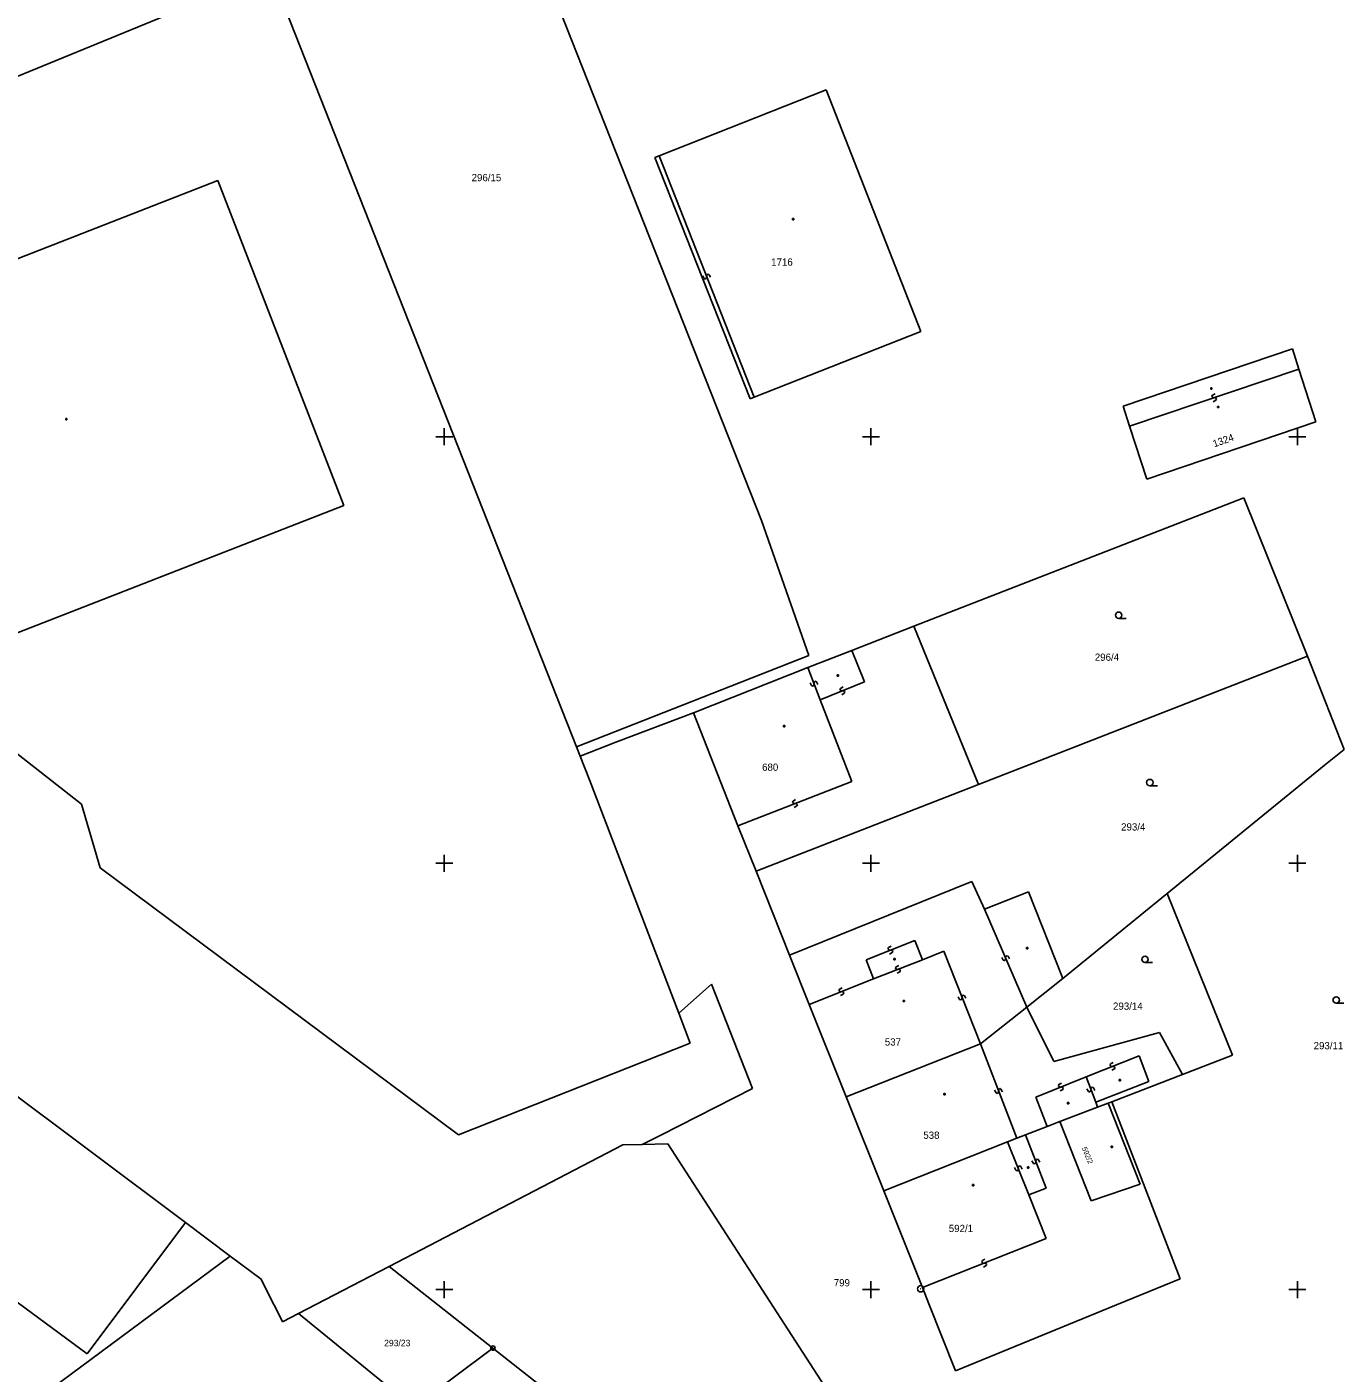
# Model space of a CAD drawing. Extents: x -492379 to -491966, y -1126153 to -1125860.
# Drawn here: x -492059.4 to -491966.7, y -1126055.9 to -1125961.2 of the extents above; entities that cross this region are included whole.
import ezdxf

# ---------------------------------------------------------------- set-up
doc = ezdxf.new("R2010")
doc.units = 0
doc.layers.add('katastrální mapa', color=7, linetype='Continuous')
doc.layers.add('síť', color=7, linetype='Continuous')

msp = doc.modelspace()

# ---------------------------------------------------------------- linework, layer by layer
at = {"layer": 'katastrální mapa'}
for p, q in [((-492033.05, -1125931.66), (-492007.69, -1125995.9)), ((-492049.8, -1125938.02), (-492020.7, -1126011.81)), ((-492074.82, -1125970.7), (-492046.06, -1125958.91)), ((-492014.89, -1125970.24), (-492003.15, -1125965.6)), ((-492003.15, -1125965.6), (-491996.49, -1125982.6)), ((-492015.19, -1125970.36), (-492014.89, -1125970.24)), ((-492015.19, -1125970.36), (-492008.49, -1125987.33)), ((-492014.89, -1125970.24), (-492008.21, -1125987.22)), ((-492063.85, -1125978.97), (-492045.92, -1125971.96)), ((-492045.92, -1125971.96), (-492037.06, -1125994.84)), ((-492005.52, -1125974.64), (-492005.43, -1125974.64)), ((-492005.52, -1125974.73), (-492005.52, -1125974.64)), ((-492005.43, -1125974.73), (-492005.52, -1125974.73)), ((-492005.43, -1125974.64), (-492005.43, -1125974.73)), ((-492011.72, -1125978.86), (-492011.83, -1125978.68)), ((-492011.65, -1125978.9), (-492011.72, -1125978.86)), ((-492011.59, -1125978.87), (-492011.65, -1125978.9)), ((-492011.56, -1125978.8), (-492011.59, -1125978.87)), ((-492011.54, -1125978.66), (-492011.56, -1125978.8)), ((-492011.51, -1125978.59), (-492011.54, -1125978.66)), ((-492011.45, -1125978.56), (-492011.51, -1125978.59)), ((-492011.38, -1125978.6), (-492011.45, -1125978.56)), ((-492011.27, -1125978.78), (-492011.38, -1125978.6)), ((-492008.21, -1125987.22), (-491996.49, -1125982.6)), ((-491982.25, -1125987.84), (-491970.35, -1125983.81)), ((-491970.35, -1125983.81), (-491969.9, -1125985.24)), ((-491981.8, -1125989.26), (-491969.9, -1125985.24)), ((-491969.9, -1125985.24), (-491968.71, -1125988.95)), ((-491976.1, -1125986.56), (-491976.01, -1125986.56)), ((-491976.1, -1125986.65), (-491976.1, -1125986.56)), ((-491976.01, -1125986.56), (-491976.01, -1125986.65)), ((-492008.49, -1125987.33), (-492008.21, -1125987.22)), ((-491976.01, -1125986.65), (-491976.1, -1125986.65)), ((-491975.97, -1125987.07), (-491976.01, -1125987.15)), ((-491976.01, -1125987.15), (-491975.99, -1125987.2)), ((-491975.99, -1125987.2), (-491975.92, -1125987.24)), ((-491975.78, -1125986.97), (-491975.97, -1125987.07)), ((-491975.92, -1125987.24), (-491975.78, -1125987.26)), ((-491975.73, -1125987.43), (-491975.92, -1125987.53)), ((-491975.78, -1125987.26), (-491975.71, -1125987.3)), ((-491975.69, -1125987.35), (-491975.73, -1125987.43)), ((-491975.71, -1125987.3), (-491975.69, -1125987.35)), ((-491982.25, -1125987.84), (-491981.8, -1125989.26)), ((-491975.62, -1125987.86), (-491975.53, -1125987.86)), ((-491975.62, -1125987.95), (-491975.62, -1125987.86)), ((-491975.53, -1125987.95), (-491975.62, -1125987.95)), ((-491975.53, -1125987.86), (-491975.53, -1125987.95)), ((-492056.63, -1125988.72), (-492056.54, -1125988.72)), ((-492056.63, -1125988.81), (-492056.63, -1125988.72)), ((-492056.54, -1125988.81), (-492056.63, -1125988.81)), ((-492056.54, -1125988.72), (-492056.54, -1125988.81)), ((-491981.8, -1125989.26), (-491980.6, -1125992.98)), ((-491980.6, -1125992.98), (-491968.71, -1125988.95)), ((-492062.15, -1126004.61), (-492037.06, -1125994.84)), ((-491996.98, -1126003.33), (-491973.76, -1125994.3)), ((-491973.76, -1125994.3), (-491969.3, -1126005.44)), ((-492007.69, -1125995.9), (-492004.36, -1126005.38)), ((-492001.35, -1126005.03), (-491996.98, -1126003.33)), ((-491996.98, -1126003.33), (-491992.42, -1126014.46)), ((-491982.57, -1126002.78), (-491982.04, -1126002.78)), ((-492020.7, -1126011.81), (-492004.36, -1126005.38)), ((-492004.44, -1126006.23), (-492001.35, -1126005.03)), ((-492001.35, -1126005.03), (-492000.45, -1126007.23)), ((-491992.42, -1126014.46), (-491969.3, -1126005.44)), ((-491969.3, -1126005.44), (-491966.72, -1126011.99)), ((-492012.48, -1126009.42), (-492004.44, -1126006.23)), ((-492004.44, -1126006.23), (-492003.56, -1126008.51)), ((-492004.17, -1126007.5), (-492004.28, -1126007.32)), ((-492003.99, -1126007.3), (-492004.01, -1126007.44)), ((-492003.96, -1126007.23), (-492003.99, -1126007.3)), ((-492003.9, -1126007.2), (-492003.96, -1126007.23)), ((-492003.83, -1126007.24), (-492003.9, -1126007.2)), ((-492003.72, -1126007.42), (-492003.83, -1126007.24)), ((-492003.56, -1126008.51), (-492000.45, -1126007.23)), ((-492002.36, -1126006.74), (-492002.27, -1126006.74)), ((-492002.36, -1126006.83), (-492002.36, -1126006.74)), ((-492002.27, -1126006.83), (-492002.36, -1126006.83)), ((-492002.27, -1126006.74), (-492002.27, -1126006.83)), ((-492004.1, -1126007.54), (-492004.17, -1126007.5)), ((-492004.04, -1126007.51), (-492004.1, -1126007.54)), ((-492004.01, -1126007.44), (-492004.04, -1126007.51)), ((-492002.14, -1126007.7), (-492002.17, -1126007.78)), ((-492002.17, -1126007.78), (-492002.15, -1126007.83)), ((-492002.15, -1126007.83), (-492002.07, -1126007.87)), ((-492001.96, -1126007.59), (-492002.14, -1126007.7)), ((-492002.07, -1126007.87), (-492001.94, -1126007.87)), ((-492001.87, -1126008.04), (-492002.05, -1126008.15)), ((-492001.94, -1126007.87), (-492001.86, -1126007.91)), ((-492001.84, -1126007.96), (-492001.87, -1126008.04)), ((-492001.86, -1126007.91), (-492001.84, -1126007.96)), ((-492003.56, -1126008.51), (-492001.33, -1126014.24)), ((-492017.93, -1126011.48), (-492012.48, -1126009.42)), ((-492012.48, -1126009.42), (-492009.35, -1126017.36)), ((-492006.14, -1126010.32), (-492006.05, -1126010.32)), ((-492006.14, -1126010.41), (-492006.14, -1126010.32)), ((-492006.05, -1126010.41), (-492006.14, -1126010.41)), ((-492006.05, -1126010.32), (-492006.05, -1126010.41)), ((-492060.51, -1126011.92), (-492055.51, -1126015.84)), ((-492020.7, -1126011.81), (-492020.44, -1126012.46)), ((-492020.44, -1126012.46), (-492017.93, -1126011.48)), ((-491968.11, -1126013.12), (-491966.72, -1126011.99)), ((-492020.44, -1126012.46), (-492019.8, -1126014.14)), ((-491979.16, -1126022.13), (-491968.11, -1126013.12)), ((-492019.8, -1126014.14), (-492013.51, -1126030.54)), ((-492009.35, -1126017.36), (-492001.33, -1126014.24)), ((-491995.5, -1126015.66), (-491992.42, -1126014.46)), ((-491980.38, -1126014.55), (-491979.85, -1126014.55)), ((-492055.51, -1126015.84), (-492054.2, -1126020.33)), ((-492008.07, -1126020.56), (-491995.5, -1126015.66)), ((-492005.47, -1126015.63), (-492005.51, -1126015.7)), ((-492005.51, -1126015.7), (-492005.48, -1126015.76)), ((-492005.48, -1126015.76), (-492005.41, -1126015.79)), ((-492005.29, -1126015.52), (-492005.47, -1126015.63)), ((-492005.41, -1126015.79), (-492005.27, -1126015.81)), ((-492005.27, -1126015.81), (-492005.2, -1126015.84)), ((-492005.17, -1126015.9), (-492005.21, -1126015.97)), ((-492005.2, -1126015.84), (-492005.17, -1126015.9)), ((-492005.21, -1126015.97), (-492005.39, -1126016.08)), ((-492009.35, -1126017.36), (-492008.07, -1126020.56)), ((-492054.2, -1126020.33), (-492029.01, -1126039.11)), ((-492008.07, -1126020.56), (-492005.72, -1126026.47)), ((-492005.72, -1126026.47), (-491992.9, -1126021.28)), ((-491992.9, -1126021.28), (-491992, -1126023.23)), ((-491992, -1126023.23), (-491988.91, -1126022.01)), ((-491988.91, -1126022.01), (-491986.51, -1126028.12)), ((-491986.51, -1126028.12), (-491979.16, -1126022.13)), ((-491979.16, -1126022.13), (-491974.57, -1126033.5)), ((-491992, -1126023.23), (-491989.04, -1126030.13)), ((-492000.34, -1126026.79), (-491996.92, -1126025.44)), ((-491998.76, -1126025.94), (-491998.8, -1126026.02)), ((-491998.8, -1126026.02), (-491998.77, -1126026.08)), ((-491998.77, -1126026.08), (-491998.7, -1126026.11)), ((-491998.58, -1126025.84), (-491998.76, -1126025.94)), ((-491998.7, -1126026.11), (-491998.56, -1126026.12)), ((-491998.5, -1126026.29), (-491998.68, -1126026.39)), ((-491998.56, -1126026.12), (-491998.49, -1126026.15)), ((-491998.46, -1126026.21), (-491998.5, -1126026.29)), ((-491998.49, -1126026.15), (-491998.46, -1126026.21)), ((-491996.92, -1126025.44), (-491996.38, -1126026.79)), ((-491996.38, -1126026.79), (-491994.88, -1126026.19)), ((-491994.88, -1126026.19), (-491992.3, -1126032.71)), ((-491989.06, -1126025.94), (-491988.97, -1126025.94)), ((-491989.06, -1126026.03), (-491989.06, -1126025.94)), ((-491988.97, -1126026.03), (-491989.06, -1126026.03)), ((-491988.97, -1126025.94), (-491988.97, -1126026.03)), ((-492005.72, -1126026.47), (-492004.34, -1126029.93)), ((-492000.34, -1126026.79), (-491999.81, -1126028.14)), ((-491999.81, -1126028.14), (-491996.38, -1126026.79)), ((-491998.39, -1126026.71), (-491998.3, -1126026.71)), ((-491998.39, -1126026.8), (-491998.39, -1126026.71)), ((-491998.3, -1126026.8), (-491998.39, -1126026.8)), ((-491998.3, -1126026.71), (-491998.3, -1126026.8)), ((-491998.23, -1126027.29), (-491998.26, -1126027.37)), ((-491998.04, -1126027.19), (-491998.23, -1126027.29)), ((-491990.69, -1126026.82), (-491990.8, -1126026.64)), ((-491990.61, -1126026.85), (-491990.69, -1126026.82)), ((-491990.56, -1126026.83), (-491990.61, -1126026.85)), ((-491990.52, -1126026.75), (-491990.56, -1126026.83)), ((-491990.48, -1126026.53), (-491990.52, -1126026.61)), ((-491990.52, -1126026.61), (-491990.52, -1126026.75)), ((-491990.43, -1126026.51), (-491990.48, -1126026.53)), ((-491990.35, -1126026.54), (-491990.43, -1126026.51)), ((-491990.24, -1126026.72), (-491990.35, -1126026.54)), ((-491980.72, -1126026.99), (-491980.19, -1126026.99)), ((-492004.34, -1126029.93), (-491999.81, -1126028.14)), ((-491998.26, -1126027.37), (-491998.24, -1126027.43)), ((-491998.24, -1126027.43), (-491998.16, -1126027.46)), ((-491998.16, -1126027.46), (-491998.03, -1126027.47)), ((-491997.96, -1126027.64), (-491998.15, -1126027.74)), ((-491998.03, -1126027.47), (-491997.95, -1126027.5)), ((-491997.93, -1126027.56), (-491997.96, -1126027.64)), ((-491997.95, -1126027.5), (-491997.93, -1126027.56)), ((-491989.04, -1126030.13), (-491986.51, -1126028.12)), ((-492013.51, -1126030.54), (-492011.21, -1126028.51)), ((-492011.21, -1126028.51), (-492008.32, -1126035.85)), ((-492002.21, -1126028.86), (-492002.24, -1126028.94)), ((-492002.24, -1126028.94), (-492002.22, -1126029)), ((-492002.22, -1126029), (-492002.14, -1126029.03)), ((-492002.02, -1126028.76), (-492002.21, -1126028.86)), ((-492002.14, -1126029.03), (-492002.01, -1126029.04)), ((-492002.01, -1126029.04), (-492001.93, -1126029.07)), ((-492001.91, -1126029.13), (-492001.94, -1126029.21)), ((-492001.93, -1126029.07), (-492001.91, -1126029.13)), ((-492004.34, -1126029.93), (-492001.74, -1126036.44)), ((-492001.94, -1126029.21), (-492002.13, -1126029.31)), ((-491997.73, -1126029.65), (-491997.64, -1126029.65)), ((-491997.73, -1126029.74), (-491997.73, -1126029.65)), ((-491997.64, -1126029.74), (-491997.73, -1126029.74)), ((-491997.64, -1126029.65), (-491997.64, -1126029.74)), ((-491993.76, -1126029.58), (-491993.87, -1126029.4)), ((-491993.69, -1126029.62), (-491993.76, -1126029.58)), ((-491993.63, -1126029.59), (-491993.69, -1126029.62)), ((-491993.6, -1126029.52), (-491993.63, -1126029.59)), ((-491993.58, -1126029.38), (-491993.6, -1126029.52)), ((-491993.55, -1126029.31), (-491993.58, -1126029.38)), ((-491993.49, -1126029.28), (-491993.55, -1126029.31)), ((-491993.42, -1126029.32), (-491993.49, -1126029.28)), ((-491993.31, -1126029.5), (-491993.42, -1126029.32)), ((-491992.3, -1126032.71), (-491989.04, -1126030.13)), ((-491989.04, -1126030.13), (-491987.14, -1126033.96)), ((-491967.27, -1126029.85), (-491966.74, -1126029.85)), ((-492068.35, -1126030.18), (-492048.21, -1126045.28)), ((-492013.51, -1126030.54), (-492012.7, -1126032.67)), ((-491987.14, -1126033.96), (-491979.71, -1126031.9)), ((-491979.71, -1126031.9), (-491978.09, -1126034.86)), ((-492029.01, -1126039.11), (-492012.7, -1126032.67)), ((-492001.74, -1126036.44), (-491992.3, -1126032.71)), ((-491992.3, -1126032.71), (-491989.74, -1126039.34)), ((-491984.87, -1126035.04), (-491981.14, -1126033.55)), ((-491981.14, -1126033.55), (-491980.44, -1126035.36)), ((-491978.09, -1126034.86), (-491974.57, -1126033.5)), ((-491983.14, -1126034.12), (-491983.17, -1126034.2)), ((-491983.17, -1126034.2), (-491983.15, -1126034.26)), ((-491983.15, -1126034.26), (-491983.07, -1126034.29)), ((-491982.95, -1126034.02), (-491983.14, -1126034.12)), ((-491983.07, -1126034.29), (-491982.94, -1126034.3)), ((-491982.87, -1126034.47), (-491983.06, -1126034.57)), ((-491983.06, -1126036.78), (-491978.09, -1126034.86)), ((-491982.94, -1126034.3), (-491982.86, -1126034.33)), ((-491982.84, -1126034.39), (-491982.87, -1126034.47)), ((-491982.86, -1126034.33), (-491982.84, -1126034.39)), ((-491988.41, -1126036.45), (-491984.87, -1126035.04)), ((-491986.77, -1126035.57), (-491986.81, -1126035.65)), ((-491986.81, -1126035.65), (-491986.78, -1126035.71)), ((-491986.78, -1126035.71), (-491986.71, -1126035.74)), ((-491986.59, -1126035.47), (-491986.77, -1126035.57)), ((-491986.71, -1126035.74), (-491986.57, -1126035.75)), ((-491986.57, -1126035.75), (-491986.5, -1126035.78)), ((-491986.5, -1126035.78), (-491986.47, -1126035.84)), ((-491984.87, -1126035.04), (-491984.18, -1126036.82)), ((-491984.48, -1126035.79), (-491984.52, -1126035.86)), ((-491984.43, -1126035.76), (-491984.48, -1126035.79)), ((-491984.35, -1126035.8), (-491984.43, -1126035.76)), ((-491984.25, -1126035.98), (-491984.35, -1126035.8)), ((-491984.18, -1126036.82), (-491980.44, -1126035.36)), ((-491982.54, -1126035.21), (-491982.45, -1126035.21)), ((-491982.54, -1126035.3), (-491982.54, -1126035.21)), ((-491982.45, -1126035.3), (-491982.54, -1126035.3)), ((-491982.45, -1126035.21), (-491982.45, -1126035.3)), ((-492014.77, -1126039.13), (-492008.32, -1126035.85)), ((-492001.74, -1126036.44), (-491999.1, -1126043.04)), ((-491994.87, -1126036.21), (-491994.78, -1126036.21)), ((-491994.87, -1126036.3), (-491994.87, -1126036.21)), ((-491994.78, -1126036.3), (-491994.87, -1126036.3)), ((-491994.78, -1126036.21), (-491994.78, -1126036.3)), ((-491991.19, -1126036.16), (-491991.3, -1126035.97)), ((-491991.12, -1126036.19), (-491991.19, -1126036.16)), ((-491991.06, -1126036.17), (-491991.12, -1126036.19)), ((-491991.03, -1126036.09), (-491991.06, -1126036.17)), ((-491991.01, -1126035.96), (-491991.03, -1126036.09)), ((-491990.98, -1126035.88), (-491991.01, -1126035.96)), ((-491990.92, -1126035.86), (-491990.98, -1126035.88)), ((-491990.85, -1126035.89), (-491990.92, -1126035.86)), ((-491990.74, -1126036.08), (-491990.85, -1126035.89)), ((-491988.41, -1126036.45), (-491987.61, -1126038.53)), ((-491986.51, -1126035.92), (-491986.69, -1126036.02)), ((-491986.47, -1126035.84), (-491986.51, -1126035.92)), ((-491984.7, -1126036.06), (-491984.8, -1126035.88)), ((-491984.62, -1126036.1), (-491984.7, -1126036.06)), ((-491984.57, -1126036.07), (-491984.62, -1126036.1)), ((-491984.53, -1126036), (-491984.57, -1126036.07)), ((-491984.52, -1126035.86), (-491984.53, -1126036)), ((-491986.71, -1126038.18), (-491984.05, -1126037.16)), ((-491986.16, -1126036.84), (-491986.07, -1126036.84)), ((-491986.16, -1126036.93), (-491986.16, -1126036.84)), ((-491986.07, -1126036.93), (-491986.16, -1126036.93)), ((-491986.07, -1126036.84), (-491986.07, -1126036.93)), ((-491984.18, -1126036.82), (-491984.05, -1126037.16)), ((-491984.05, -1126037.16), (-491983.31, -1126036.87)), ((-491983.31, -1126036.87), (-491983.06, -1126036.78)), ((-491983.31, -1126036.87), (-491981.05, -1126042.57)), ((-491983.06, -1126036.78), (-491978.24, -1126049.25)), ((-491989.13, -1126039.11), (-491987.61, -1126038.53)), ((-491987.61, -1126038.53), (-491986.71, -1126038.18)), ((-491986.71, -1126038.18), (-491984.5, -1126043.75)), ((-492016.08, -1126039.79), (-492014.77, -1126039.13)), ((-491999.1, -1126043.04), (-491990.38, -1126039.59)), ((-491990.38, -1126039.59), (-491989.74, -1126039.34)), ((-491990.38, -1126039.59), (-491988.89, -1126043.34)), ((-491989.74, -1126039.34), (-491989.13, -1126039.11)), ((-491989.13, -1126039.11), (-491987.67, -1126042.86)), ((-492033.88, -1126048.37), (-492017.45, -1126039.82)), ((-492017.45, -1126039.82), (-492016.08, -1126039.79)), ((-492016.08, -1126039.79), (-492014.28, -1126039.75)), ((-492014.28, -1126039.75), (-491999, -1126063.33)), ((-491983.1, -1126039.91), (-491983.01, -1126039.91)), ((-491983.1, -1126040), (-491983.1, -1126039.91)), ((-491983.01, -1126040), (-491983.1, -1126040)), ((-491983.01, -1126039.91), (-491983.01, -1126040)), ((-491989.81, -1126041.6), (-491989.91, -1126041.41)), ((-491989.63, -1126041.4), (-491989.64, -1126041.53)), ((-491989.6, -1126041.32), (-491989.63, -1126041.4)), ((-491989.54, -1126041.3), (-491989.6, -1126041.32)), ((-491989.46, -1126041.33), (-491989.54, -1126041.3)), ((-491989.36, -1126041.52), (-491989.46, -1126041.33)), ((-491988.99, -1126041.36), (-491988.9, -1126041.36)), ((-491988.99, -1126041.45), (-491988.99, -1126041.36)), ((-491988.9, -1126041.45), (-491988.99, -1126041.45)), ((-491988.9, -1126041.36), (-491988.9, -1126041.45)), ((-491988.57, -1126041.12), (-491988.68, -1126040.93)), ((-491988.5, -1126041.15), (-491988.57, -1126041.12)), ((-491988.44, -1126041.13), (-491988.5, -1126041.15)), ((-491988.41, -1126041.05), (-491988.44, -1126041.13)), ((-491988.39, -1126040.92), (-491988.41, -1126041.05)), ((-491988.36, -1126040.84), (-491988.39, -1126040.92)), ((-491988.3, -1126040.82), (-491988.36, -1126040.84)), ((-491988.23, -1126040.85), (-491988.3, -1126040.82)), ((-491988.12, -1126041.04), (-491988.23, -1126040.85)), ((-491989.73, -1126041.63), (-491989.81, -1126041.6)), ((-491989.67, -1126041.61), (-491989.73, -1126041.63)), ((-491989.64, -1126041.53), (-491989.67, -1126041.61)), ((-491999.1, -1126043.04), (-491996.38, -1126049.86)), ((-491992.85, -1126042.6), (-491992.76, -1126042.6)), ((-491992.85, -1126042.69), (-491992.85, -1126042.6)), ((-491992.76, -1126042.69), (-491992.85, -1126042.69)), ((-491992.76, -1126042.6), (-491992.76, -1126042.69)), ((-491988.89, -1126043.34), (-491987.67, -1126042.86)), ((-491988.89, -1126043.34), (-491987.68, -1126046.41)), ((-491984.5, -1126043.75), (-491981.05, -1126042.57)), ((-492055.13, -1126054.51), (-492048.21, -1126045.28)), ((-492048.21, -1126045.28), (-492045.05, -1126047.65)), ((-491996.38, -1126049.86), (-491987.68, -1126046.41)), ((-492059.9, -1126058.64), (-492045.05, -1126047.65)), ((-492045.05, -1126047.65), (-492042.89, -1126049.27)), ((-491992.16, -1126047.96), (-491992.2, -1126048.04)), ((-491992.2, -1126048.04), (-491992.17, -1126048.1)), ((-491992.17, -1126048.1), (-491992.1, -1126048.13)), ((-491991.98, -1126047.86), (-491992.16, -1126047.96)), ((-491992.1, -1126048.13), (-491991.96, -1126048.14)), ((-492062.66, -1126048.96), (-492055.13, -1126054.51)), ((-492035.25, -1126049.08), (-492033.88, -1126048.37)), ((-492026.58, -1126054.11), (-492033.88, -1126048.37)), ((-491991.9, -1126048.31), (-491992.08, -1126048.41)), ((-491991.96, -1126048.14), (-491991.89, -1126048.17)), ((-491991.86, -1126048.23), (-491991.9, -1126048.31)), ((-491991.89, -1126048.17), (-491991.86, -1126048.23)), ((-492042.89, -1126049.27), (-492042.43, -1126050.17)), ((-492040.25, -1126051.68), (-492035.25, -1126049.08)), ((-491996.38, -1126049.86), (-491995.93, -1126050.99)), ((-491983.24, -1126051.29), (-491978.24, -1126049.25)), ((-492042.43, -1126050.17), (-492041.53, -1126051.96)), ((-492041.37, -1126052.27), (-492040.25, -1126051.68)), ((-492040.25, -1126051.68), (-492032.16, -1126058.28)), ((-491995.93, -1126050.99), (-491994.04, -1126055.72)), ((-491994.04, -1126055.72), (-491983.24, -1126051.29)), ((-492041.53, -1126051.96), (-492041.37, -1126052.27)), ((-492031.93, -1126058.1), (-492026.58, -1126054.11)), ((-492016.89, -1126061.73), (-492026.58, -1126054.11))]:
    msp.add_line(p, q, dxfattribs=at)
for centre, radius in [((-491982.57, -1126002.555), 0.225), ((-491980.38, -1126014.325), 0.225), ((-491980.72, -1126026.765), 0.225), ((-491967.27, -1126029.625), 0.225), ((-491996.5, -1126049.94), 0.225), ((-491996.5, -1126049.94), 0.003), ((-492026.58, -1126054.11), 0.15), ((-492026.58, -1126054.11), 0.003)]:
    msp.add_circle(centre, radius, dxfattribs=at)
at = {"layer": 'síť'}
for p, q in [((-492030, -1125989.4), (-492030, -1125990.6)), ((-492000, -1125989.4), (-492000, -1125990.6)), ((-491970, -1125989.4), (-491970, -1125990.6)), ((-492030.6, -1125990), (-492029.4, -1125990)), ((-492000.6, -1125990), (-491999.4, -1125990)), ((-491970.6, -1125990), (-491969.4, -1125990)), ((-492030, -1126019.4), (-492030, -1126020.6)), ((-492000, -1126019.4), (-492000, -1126020.6)), ((-491970, -1126019.4), (-491970, -1126020.6)), ((-492030.6, -1126020), (-492029.4, -1126020)), ((-492000.6, -1126020), (-491999.4, -1126020)), ((-491970.6, -1126020), (-491969.4, -1126020)), ((-492030.6, -1126050), (-492029.4, -1126050)), ((-492030, -1126049.4), (-492030, -1126050.6)), ((-492000.6, -1126050), (-491999.4, -1126050)), ((-492000, -1126049.4), (-492000, -1126050.6)), ((-491970.6, -1126050), (-491969.4, -1126050)), ((-491970, -1126049.4), (-491970, -1126050.6))]:
    msp.add_line(p, q, dxfattribs=at)

# ---------------------------------------------------------------- texts
at = {"layer": 'katastrální mapa'}
for s, height, p in [('296/15', 0.51, (-492028.08, -1125972.02)), ('1716', 0.51, (-492007.01, -1125977.96)), ('296/4', 0.51, (-491984.25, -1126005.76)), ('680', 0.51, (-492007.65, -1126013.5)), ('293/4', 0.51, (-491982.4, -1126017.7)), ('293/14', 0.51, (-491982.97, -1126030.31)), ('537', 0.51, (-491999.02, -1126032.83)), ('293/11', 0.51, (-491968.86, -1126033.09)), ('538', 0.51, (-491996.31, -1126039.39)), ('592/1', 0.51, (-491994.52, -1126045.95)), ('799', 0.51, (-492002.61, -1126049.77)), ('293/23', 0.45, (-492034.23, -1126053.98))]:
    msp.add_text(s, height=height, dxfattribs=at).set_placement(p)
for s, height, rotation, p in [('1324', 0.51, 19.368, (-491975.85, -1125990.75)), ('592/2', 0.36, 292.896, (-491985.17, -1126040.05))]:
    msp.add_text(s, height=height, rotation=rotation, dxfattribs=at).set_placement(p)

doc.saveas('drawing.dxf')
